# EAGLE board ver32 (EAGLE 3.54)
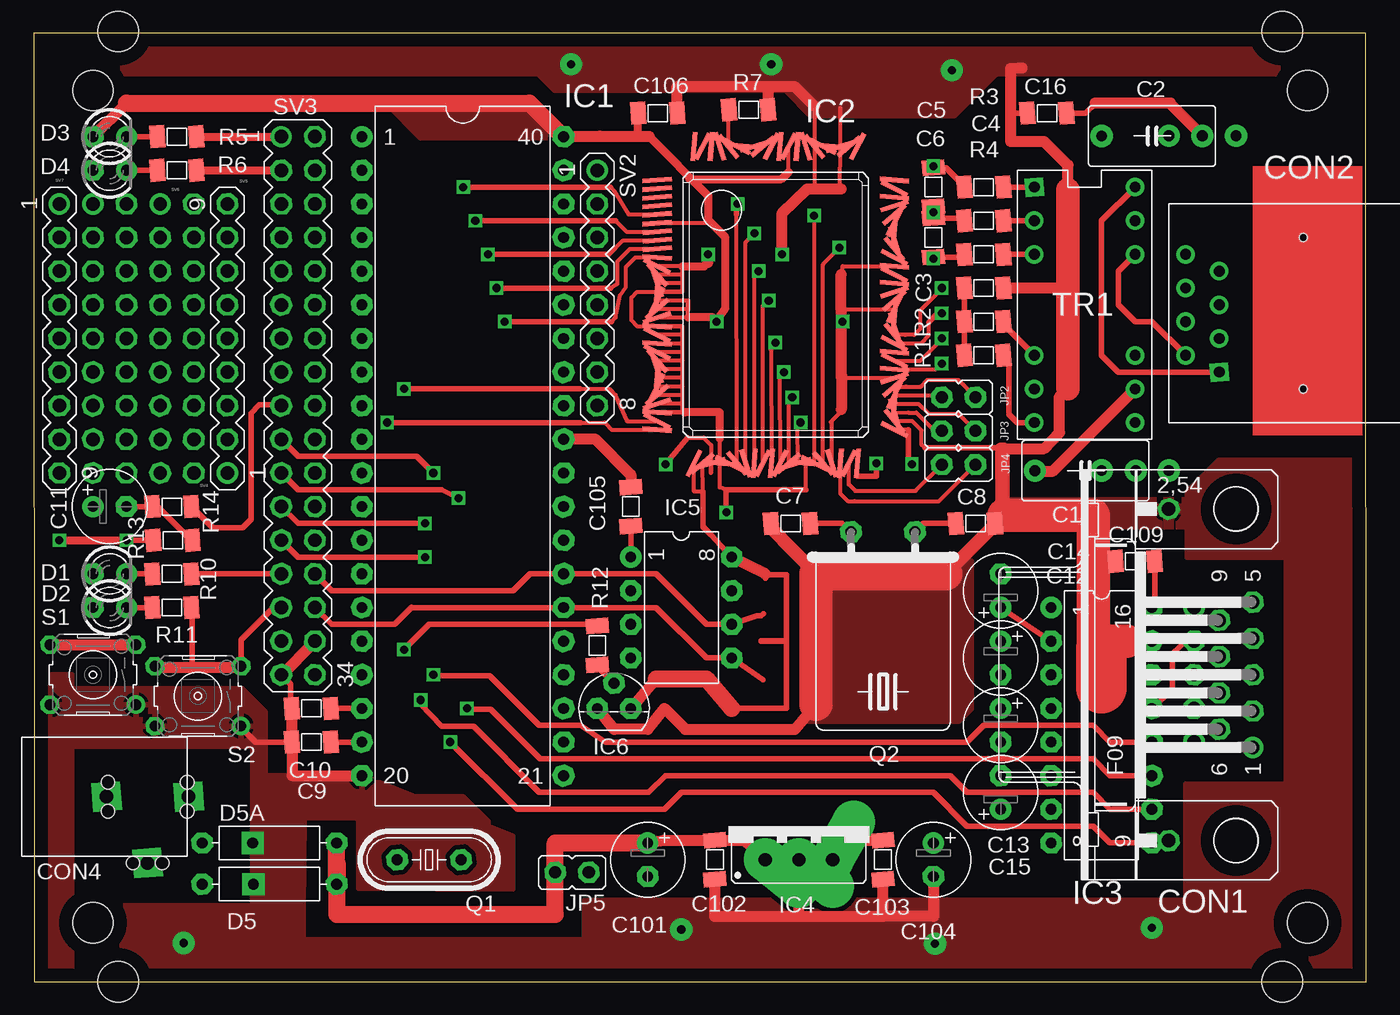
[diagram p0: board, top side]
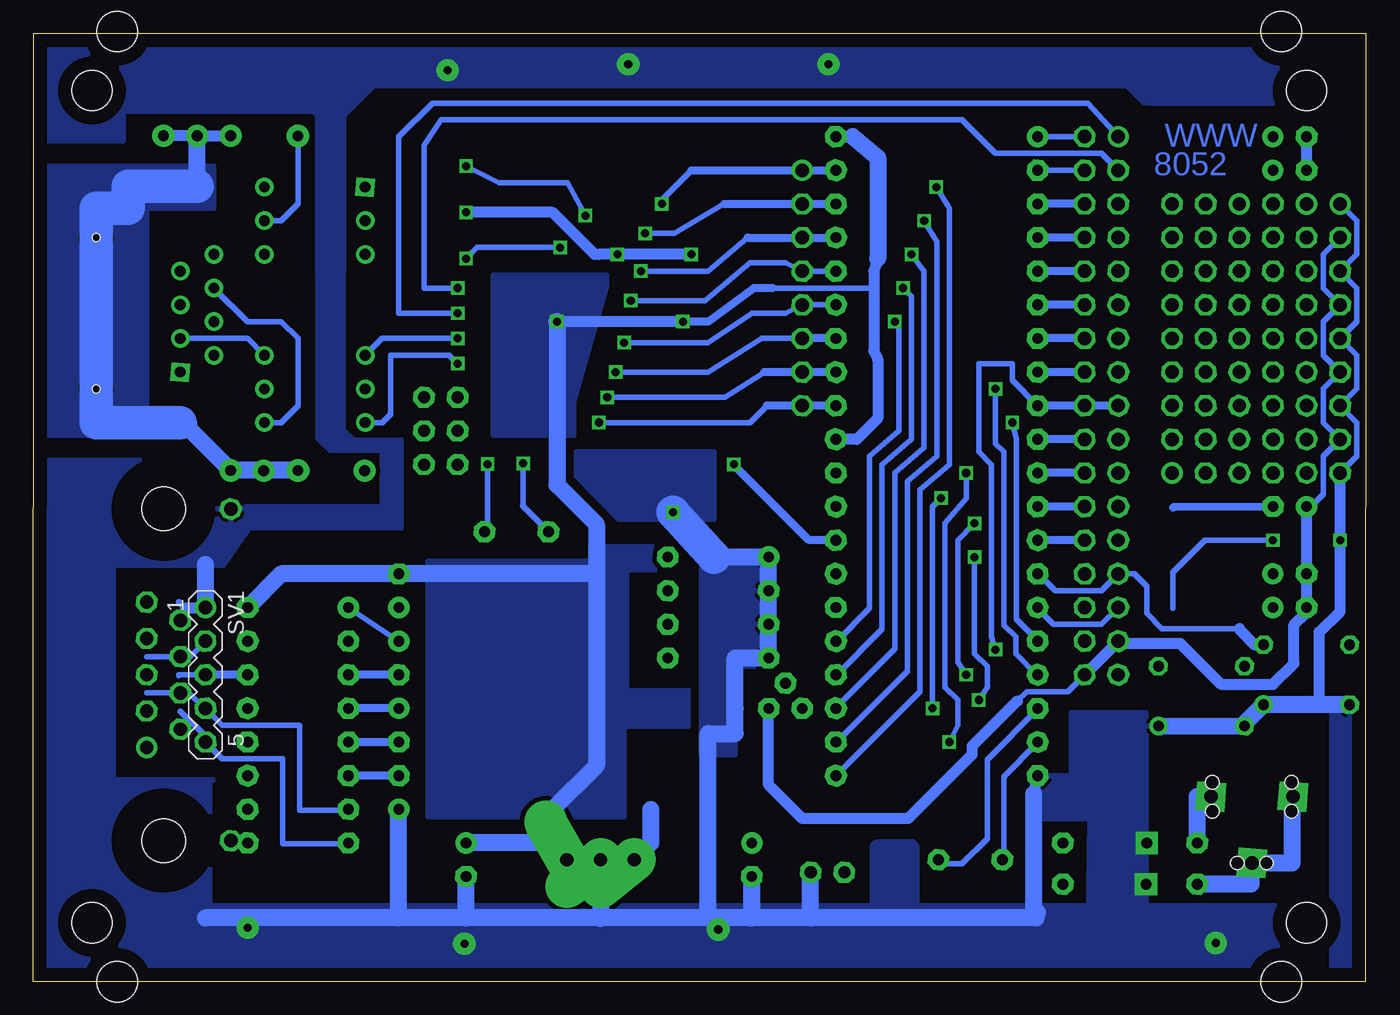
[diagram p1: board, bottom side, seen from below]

Size 100.68 x 71.65 mm. Coordinates in mm from the lower left corner, seen from the top.
Outline: 0.02,0.01 100.68,0 100.65,71.65 0,71.65 0.02,0.01
Copper layers used: Top, Bottom
Holes 3.05 mm at 4.47,67.32 4.47,4.45 96.23,4.45 96.23,67.32 6.38,0.01 6.38,71.76 94.32,71.76 94.32,0.01

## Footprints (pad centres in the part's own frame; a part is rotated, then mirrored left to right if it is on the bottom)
P75 = drill 0.813 pad 1.676 round:  -3.81,0;  3.81,0
06 = smd 1.143 x 1.702 rotated 4.4:  1.473,0 | smd 1.143 x 1.702 rotated 4.3:  -1.473,0
,5-6 = drill 0.813 pad 1.6 octagon:  1.27,0 | drill 0.813 pad 1.6 round:  -1.27,0
9H = drill 1.016 pad 1.6 round:  -5.486,-1.27 | drill 1.016 pad 1.6 octagon:  -2.743,-1.27;  0,-1.27;  2.743,-1.27;  5.486,-1.27;  -4.115,1.27;  -1.372,1.27;  1.372,1.27;  4.115,1.27;  -12.522,5.08;  12.522,5.08 | hole 3.302: -12.522,0; 12.522,0
45A = drill 0.813 pad 1.397 square:  5.08,1.27 | drill 0.813 pad 1.397 round:  2.54,1.27;  0,1.27;  -2.54,1.27;  3.81,-1.27;  1.27,-1.27;  -1.27,-1.27;  -3.81,-1.27 | hole 0.61: -5.08,7.62; 6.35,7.62
SOC = drill 1.016 pad 2.184 square:  0,5;  3.1,0;  -3.1,0 | hole 1.016: -3,1.1; -3,-1.1; 3,1.1; 3,-1.1; 1.1,5; -1.1,5
D3 = drill 0.813 pad 1.6 octagon:  -1.27,0 | drill 0.813 pad 1.6 round:  1.27,0
10 = drill 0.813 pad 1.6 octagon:  -5.08,0;  5.08,0
L40 = drill 0.813 pad 1.6 round:  -24.13,-7.62 | drill 0.813 pad 1.6 octagon:  -21.59,-7.62;  -19.05,-7.62;  -16.51,-7.62;  -13.97,-7.62;  -11.43,-7.62;  -8.89,-7.62;  -6.35,-7.62;  -3.81,-7.62;  -1.27,-7.62;  1.27,-7.62;  3.81,-7.62;  6.35,-7.62;  8.89,-7.62;  11.43,-7.62;  13.97,-7.62;  16.51,-7.62;  19.05,-7.62;  21.59,-7.62;  24.13,-7.62;  24.13,7.62;  21.59,7.62;  19.05,7.62;  16.51,7.62;  13.97,7.62;  11.43,7.62;  8.89,7.62;  6.35,7.62;  3.81,7.62;  1.27,7.62;  -1.27,7.62;  -3.81,7.62;  -6.35,7.62;  -8.89,7.62;  -11.43,7.62;  -13.97,7.62;  -16.51,7.62;  -19.05,7.62;  -21.59,7.62;  -24.13,7.62
P100 = smd 0.35 x 2.2 rotated 4.3:  -9.425,-8.965;  -3.575,-8.965 | smd 0.35 x 2.2 rotated 4.4:  -8.775,-8.965;  2.925,-8.965 | smd 0.35 x 2.2 rotated 4.5:  -8.125,-8.965;  9.425,-8.965 | smd 0.35 x 2.2 rotated 4.6:  -7.475,-8.965 | smd 0.35 x 2.2 rotated 4.7:  -6.825,-8.965;  -6.175,-8.965;  3.575,8.965 | smd 0.35 x 2.2 rotated 4.8:  -5.525,-8.965;  -2.925,8.965 | smd 0.35 x 2.2 rotated 4.9:  -4.875,-8.965;  -9.425,8.965 | smd 0.35 x 2.2 rotated 5:  -4.225,-8.965 | smd 0.35 x 2.2 rotated 26.8:  -2.925,-8.965 | smd 0.35 x 2.2 rotated 49.3:  -2.275,-8.965 | smd 0.35 x 2.2 rotated 71.8:  -1.625,-8.965 | smd 0.35 x 2.2 rotated 94.3:  -0.975,-8.965 | smd 0.35 x 2.2 rotated 116.8:  -0.325,-8.965 | smd 0.35 x 2.2 rotated 139.3:  0.325,-8.965 | smd 0.35 x 2.2 rotated 161.8:  0.975,-8.965 | smd 0.35 x 2.2 rotated 184.3:  1.625,-8.965 | smd 0.35 x 2.2 rotated 206.8:  2.275,-8.965 | smd 0.35 x 2.2 rotated 26.9:  3.575,-8.965 | smd 0.35 x 2.2 rotated 49.4:  4.225,-8.965 | smd 0.35 x 2.2 rotated 71.9:  4.875,-8.965 | smd 0.35 x 2.2 rotated 94.4:  5.525,-8.965 | smd 0.35 x 2.2 rotated 116.9:  6.175,-8.965 | smd 0.35 x 2.2 rotated 139.4:  6.825,-8.965 | smd 0.35 x 2.2 rotated 161.9:  7.475,-8.965 | smd 0.35 x 2.2 rotated 184.4:  8.125,-8.965 | smd 0.35 x 2.2 rotated 206.9:  8.775,-8.965 | smd 0.35 x 2.2 rotated 27.2:  9.425,8.965;  2.925,8.965 | smd 0.35 x 2.2 rotated 49.7:  8.775,8.965;  2.275,8.965 | smd 0.35 x 2.2 rotated 72.2:  8.125,8.965;  1.625,8.965 | smd 0.35 x 2.2 rotated 94.7:  7.475,8.965;  0.975,8.965 | smd 0.35 x 2.2 rotated 117.2:  6.825,8.965;  0.325,8.965 | smd 0.35 x 2.2 rotated 162.2:  5.525,8.965;  -0.975,8.965 | smd 0.35 x 2.2 rotated 139.7:  6.175,8.965;  -0.325,8.965 | smd 0.35 x 2.2 rotated 184.7:  4.875,8.965;  -1.625,8.965 | smd 0.35 x 2.2 rotated 207.2:  4.225,8.965;  -2.275,8.965 | smd 0.35 x 2.2 rotated 27.3:  -3.575,8.965 | smd 0.35 x 2.2 rotated 49.8:  -4.225,8.965 | smd 0.35 x 2.2 rotated 72.3:  -4.875,8.965 | smd 0.35 x 2.2 rotated 94.8:  -5.525,8.965 | smd 0.35 x 2.2 rotated 117.3:  -6.175,8.965 | smd 0.35 x 2.2 rotated 139.8:  -6.825,8.965 | smd 0.35 x 2.2 rotated 162.3:  -7.475,8.965 | smd 0.35 x 2.2 rotated 184.8:  -8.125,8.965 | smd 0.35 x 2.2 rotated 207.3:  -8.775,8.965 | smd 2.2 x 0.35 rotated 27.4:  -11.965,6.175 | smd 2.2 x 0.35 rotated 49.9:  -11.965,5.525 | smd 2.2 x 0.35 rotated 72.4:  -11.965,4.875 | smd 2.2 x 0.35 rotated 94.9:  -11.965,4.225 | smd 2.2 x 0.35 rotated 117.4:  -11.965,3.575 | smd 2.2 x 0.35 rotated 162.4:  -11.965,2.275 | smd 2.2 x 0.35 rotated 139.9:  -11.965,2.925 | smd 2.2 x 0.35 rotated 184.9:  -11.965,1.625 | smd 2.2 x 0.35 rotated 207.4:  -11.965,0.975 | smd 2.2 x 0.35 rotated 5:  -11.965,0.325 | smd 2.2 x 0.35 rotated 27.5:  -11.965,-0.325 | smd 2.2 x 0.35 rotated 50:  -11.965,-0.975 | smd 2.2 x 0.35 rotated 72.5:  -11.965,-1.625 | smd 2.2 x 0.35 rotated 95:  -11.965,-2.275 | smd 2.2 x 0.35 rotated 117.5:  -11.965,-2.925 | smd 2.2 x 0.35 rotated 140:  -11.965,-3.575 | smd 2.2 x 0.35 rotated 162.5:  -11.965,-4.225 | smd 2.2 x 0.35 rotated 185:  -11.965,-4.875 | smd 2.2 x 0.35 rotated 207.5:  -11.965,-5.525 | smd 2.2 x 0.35 rotated 4.3:  -11.965,-6.175 | smd 2.2 x 0.35 rotated 27:  11.965,-6.175 | smd 2.2 x 0.35 rotated 49.5:  11.965,-5.525 | smd 2.2 x 0.35 rotated 72:  11.965,-4.875 | smd 2.2 x 0.35 rotated 94.5:  11.965,-4.225 | smd 2.2 x 0.35 rotated 117:  11.965,-3.575 | smd 2.2 x 0.35 rotated 162:  11.965,-2.275 | smd 2.2 x 0.35 rotated 139.5:  11.965,-2.925 | smd 2.2 x 0.35 rotated 184.5:  11.965,-1.625 | smd 2.2 x 0.35 rotated 207:  11.965,-0.975 | smd 2.2 x 0.35 rotated 4.6:  11.965,-0.325 | smd 2.2 x 0.35 rotated 27.1:  11.965,0.325 | smd 2.2 x 0.35 rotated 49.6:  11.965,0.975 | smd 2.2 x 0.35 rotated 72.1:  11.965,1.625 | smd 2.2 x 0.35 rotated 94.6:  11.965,2.275 | smd 2.2 x 0.35 rotated 117.1:  11.965,2.925 | smd 2.2 x 0.35 rotated 139.6:  11.965,3.575 | smd 2.2 x 0.35 rotated 162.1:  11.965,4.225 | smd 2.2 x 0.35 rotated 184.6:  11.965,4.875 | smd 2.2 x 0.35 rotated 207.1:  11.965,5.525 | smd 2.2 x 0.35 rotated 4.7:  11.965,6.175
L16 = drill 0.813 pad 1.6 round:  -8.89,-3.81 | drill 0.813 pad 1.6 octagon:  -6.35,-3.81;  -3.81,-3.81;  -1.27,-3.81;  1.27,-3.81;  3.81,-3.81;  6.35,-3.81;  8.89,-3.81;  8.89,3.81;  6.35,3.81;  3.81,3.81;  1.27,3.81;  -1.27,3.81;  -3.81,3.81;  -6.35,3.81;  -8.89,3.81
XXS = drill 1.016 pad 3.251 offset:  -2.54,-2.54;  0,-2.54;  2.54,-2.54
L8 = drill 0.813 pad 1.6 round:  -3.81,-3.81 | drill 0.813 pad 1.6 octagon:  -1.27,-3.81;  1.27,-3.81;  3.81,-3.81;  3.81,3.81;  1.27,3.81;  -1.27,3.81;  -3.81,3.81
92 = drill 0.813 pad 1.6 octagon:  1.27,-0.635;  0,1.27;  -1.27,-0.635
1 = drill 0.914 pad 1.6 octagon:  0,-1.27;  0,1.27
49/S = drill 0.813 pad 1.6 octagon:  -2.413,0;  2.413,0
49U-H = drill 0.813 pad 1.6 octagon:  -2.413,-5.08;  2.413,-5.08
F-10XX = drill 0.813 pad 1.397 round:  -3.251,2.261 | drill 0.813 pad 1.397 octagon:  -3.251,-2.261;  3.251,2.261;  3.251,-2.261
05-1 = drill 1.016 pad 1.6 round:  -5.08,0 | drill 1.016 pad 1.6 octagon:  -2.54,0;  0,0;  2.54,0;  5.08,0
08-1 = drill 1.016 pad 1.6 round:  -8.89,0 | drill 1.016 pad 1.6 octagon:  -6.35,0;  -3.81,0;  -1.27,0;  1.27,0;  3.81,0;  6.35,0;  8.89,0
17-2 = drill 1.016 pad 1.6 round:  -20.32,-1.27 | drill 1.016 pad 1.6 octagon:  -17.78,-1.27;  -15.24,-1.27;  -12.7,-1.27;  -10.16,-1.27;  -7.62,-1.27;  -20.32,1.27;  -17.78,1.27;  -15.24,1.27;  -12.7,1.27;  -10.16,1.27;  -7.62,1.27;  -5.08,-1.27;  -5.08,1.27;  -2.54,-1.27;  0,-1.27;  2.54,-1.27;  5.08,-1.27;  7.62,-1.27;  10.16,-1.27;  -2.54,1.27;  0,1.27;  2.54,1.27;  5.08,1.27;  7.62,1.27;  10.16,1.27;  12.7,-1.27;  12.7,1.27;  15.24,-1.27;  17.78,-1.27;  20.32,-1.27;  15.24,1.27;  17.78,1.27;  20.32,1.27
09-1 = drill 1.016 pad 1.6 round:  -10.16,0 | drill 1.016 pad 1.6 octagon:  -7.62,0;  -5.08,0;  -2.54,0;  0,0;  2.54,0;  5.08,0;  7.62,0;  10.16,0
LE = drill 1.016 pad 1.6 round:  -10.16,-1.27 | drill 1.016 pad 1.6 octagon:  -7.62,-1.27;  -5.08,-1.27;  -2.54,-1.27;  0,-1.27;  2.54,-1.27;  -10.16,1.27;  -7.62,1.27;  -5.08,1.27;  -2.54,1.27;  0,1.27;  2.54,1.27;  5.08,-1.27;  7.62,-1.27;  5.08,1.27;  7.62,1.27;  10.16,-1.27;  10.16,1.27
IL16 = drill 0.813 pad 1.397 square:  -5.08,7.62 | drill 0.813 pad 1.397 round:  -5.08,5.08;  -5.08,2.54;  -5.08,-5.08;  -5.08,-7.62;  -5.08,-10.16;  2.54,7.62;  2.54,5.08;  2.54,2.54;  2.54,-5.08;  2.54,-7.62;  2.54,-10.16

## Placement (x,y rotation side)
C1  1nF/2kV  [P75]  79.45,38.6 180 top
C2  1nF/2kV  [P75]  84.48,63.88 180 top
C3  10nF  [06]  71.78,52.4 0 top
C4  10nF  [06]  71.78,57.48 0 top
C5  180  [06]  67.97,60.02 90 top
C6  180  [06]  67.97,56.2 270 top
C7  33  [06]  57.18,34.62 180 top
C8  33  [06]  71.15,34.62 0 top
C9  33  [06]  20.98,18.11 0 top
C10  33  [06]  20.98,20.64 0 top
C11  22M/16VT  [,5-6]  5.74,35.88 0 top
C12  22M/16VT  [,5-6]  73.05,24.46 270 top
C13  22M/16VT  [,5-6]  73.05,19.38 270 top
C14  22M/16VT  [,5-6]  73.05,29.54 90 top
C15  22M/16VT  [,5-6]  73.05,14.29 90 top
C16  10nF  [06]  76.54,65.6 0 top
C101  47M/25VT  [,5-6]  46.38,9.21 270 top
C102  100nF  [06]  51.46,9.21 90 top
C103  100nF  [06]  64.16,9.21 90 top
C104  100M/6.3VT  [,5-6]  67.97,9.21 270 top
C105  100nF  [06]  45.11,35.88 90 top
C106  100nF  [06]  47.14,65.6 180 top
C108  100nF  [B2,5]  50.19,20.64 0 top
C109  100nF  [06]  83.21,31.76 0 top
CON1  DB9  [9H]  90.83,23.18 90 top
CON2  RJ-45  [45A]  88.29,51.12 270 top
CON4  PWCON  [SOC]  8.6,13.98 180 top
D1  [D3]  5.74,30.8 0 top
D2  [D3]  5.74,28.27 0 top
D3  [D3]  5.74,63.83 0 top
D4  [D3]  5.74,61.29 0 top
D5  DIODE-10  [10]  17.81,7.37 0 top
D5A  DIODE-10  [10]  17.81,10.48 0 top
D6  1N4101  [7,5]  14.57,32.01 90 top
D7  1N4001  [7,5]  57.81,13.03 180 top
IC1  8052  [L40]  32.41,39.7 270 top
IC2  RTL8019AS  [P100]  56.06,51.12 270 top
IC3  MAX232  [L16]  80.67,19.38 270 top
IC4  7805  [XXS]  57.81,11.76 0 top
IC5  AT24C512  [L8]  48.92,28.27 270 top
IC6  DS1833  [92]  43.84,21.28 0 top
JP2  [1]  69.88,44.14 90 top
JP3  [1]  69.88,41.6 90 top
JP4  [1]  69.88,39.06 270 top
JP5  [1]  40.67,8.26 90 top
Q1  14.74 MHz  [49/S]  29.87,9.21 180 top
Q2  20MHz  [49U-H]  64.16,28.9 180 top
R1  49R9  [06]  71.78,47.31 180 top
R2  49R9  [06]  71.78,49.85 180 top
R3  10R  [06]  71.78,60.02 0 top
R4  10R  [06]  71.78,54.94 0 top
R5  1K0  [06]  10.82,63.83 0 top
R6  1K0  [06]  10.82,61.29 0 top
R7  27K  [06]  54,65.86 180 top
R8  10K  [06']  55.14,29.28 90 top
R9  10K  [06']  55.08,24.26 90 top
R10  1K0  [06]  10.44,30.8 0 top
R11  1K0  [06]  10.44,28.27 0 top
R12  1K0  [06]  42.57,25.41 90 top
R13  10K  [06]  10.5,33.34 0 top
R14  1K0  [06]  10.44,35.88 0 top
S1  [F-10XX]  4.47,23.18 180 top
S2  [F-10XX]  12.41,21.57 180 top
SV1  MA05-1  [05-1]  87.66,23.18 270 bottom
SV2  MA08-1  [08-1]  42.57,52.4 270 top
SV3  MA17-2  [17-2]  19.96,43.51 270 top
SV4  MA09-1  [09-1]  14.63,48.59 90 top
SV5  MA09-2  [LE]  10.82,48.59 270 top
SV6  MA09-2  [LE]  5.74,48.59 270 top
SV7  MA09-1  [09-1]  1.93,48.59 270 top
TR1  FC-22  [IL16]  80.67,52.4 0 top

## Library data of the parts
C1 C2 CON2 CON4 IC2 IC5 IC6 TR1 = network
C3-C6 C106 C109 R1-R7 R10-R14 = SMD
C7-C10 C16 C102 C103 C105 C108 = CAP
C11-C15 C101 C104 = POLCAP
CON1 = SUBD-A
D1-D4 = LED
D5 D5A D6 D7 R8 R9 = DISCRETE
IC1 = INTEL
IC3 = MAXIM
IC4 = V-REG
JP2-JP5 = JUMPS
Q1 Q2 = QUARTZ
S1 S2 = Key_omro
SV1-SV7 = CON-LSTB

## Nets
+5V: C11. C14. C103. C104. C105. C106. C108. C109. D1. D2. D3. D4. D7. IC1. IC2. IC3. IC4. IC5. IC6. R8. R9. SV3. SV7.
C1: CON2. TR1.
CTS: IC3. SV3.
GND: C3. C4. C5. C6. C7. C8. C9. C10. C15. C16. C101. C102. C103. C104. C105. C106. C108. C109. CON1. D6. IC1. IC2. IC3. IC4. IC5. IC6. JP5. R7. R13. S1. S2. SV1. SV3. SV7.
GNDA: C1. C2. C16.
LED0: IC2. R5. SV3.
LED1: IC2. R6. SV3.
N$1: CON2. TR1.
N$2: CON2. TR1.
N$3: CON2. TR1.
N$4: C1. TR1.
N$5: C3. R1. R2.
N$6: C2. TR1.
N$7: C6. IC2. R4.
N$8: IC2. R7.
N$9: C5. IC2. R3.
N$10: R3. TR1.
N$11: IC2. R1. TR1.
N$12: IC2. R2. TR1.
N$13: D4. R6.
N$14: D3. R5.
N$15: C7. IC2. Q2.
N$16: C10. IC1. Q1.
N$17: C9. IC1. Q1.
N$18: D1. R10.
N$19: IC6. R12.
N$20: D2. R11.
N$21: C11. D6. R13. R14.
N$22: C8. IC2. Q2.
N$23: CON4. D5.
N$24: CON4. D5A.
N$25: C101. C102. D5. D5A. D7. IC4. JP5.
N$29: C12. IC3.
N$30: C13. IC3.
N$31: C14. IC3.
N$32: C15. IC3.
N$33: C13. IC3.
N$34: C12. IC3.
N$37_IN: CON1. IC3. SV1.
N$39_IN: CON1. IC3. SV1.
N$40: R4. TR1.
N$41: C4. TR1.
N$42: IC2. JP4.
N$43: IC2. JP4.
N$44: IC2. JP2.
N$45: IC2. JP2.
N$46: IC2. JP3.
N$47: IC2. JP3.
N$51_OUT: CON1. IC3. SV1.
NS$40_OU: CON1. IC3. SV1.
P00: IC1. IC2. SV2.
P01: IC1. IC2. SV2.
P02: IC1. IC2. SV2.
P03: IC1. IC2. SV2.
P04: IC1. IC2. SV2.
P05: IC1. IC2. SV2.
P06: IC1. IC2. SV2.
P07: IC1. IC2. SV2.
P10: IC1. SV3.
P11: IC1. SV3.
P12: IC1. SV3.
P13: IC1. SV3.
P14: IC1. SV3.
P15: IC1. SV3.
P16: IC1. SV3.
P17: IC1. SV3.
P20: IC1. IC2.
P21: IC1. IC2.
P22: IC1. IC2.
P23: IC1. IC2.
P24: IC1. IC2.
P25: IC1. IC5. R9. SV3.
P26: IC1. IC5. R8. SV3.
P27: IC1. IC2.
P30: IC1. SV3.
P31: IC1. SV3.
P32: IC1. SV3.
P33: IC1. SV3.
P34: IC1. R10. S1. SV3.
P35: IC1. R11. S2. SV3.
RD\: IC1. IC2.
RST: IC1. R12. R14. SV3.
RTS: IC3. SV3.
RXD: IC3. SV3.
TXD: IC3. SV3.
WR\: IC1. IC2.

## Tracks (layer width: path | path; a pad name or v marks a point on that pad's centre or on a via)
+5V  (via drill 0.61 pad 1.02)
  Top 0.305: 60.28,39.16 60.25,42.29 60.22,42.29 61.1,43.16 | 65.02,54.05 61.11,54.05 61.03,50.82 60.97,50.78 | 47.09,57.3 50.94,57.3 50.95,57.48 | 61.11,45.6 65.02,45.6 | 60.97,50.78 65.02,50.8 | 60.97,50.78 60.99,50.8 | 49.44,50.74 49.44,51.45 | 49.44,50.8 47.09,50.8 | 47.09,50.15 49,50.15 49.44,50.17 49.44,50.74 | 49.44,51.45 47.09,51.45 | 49.44,50.74 49.44,50.8 | 49.44,51.45 49.44,50.8 | 51.59,49.92 51.33,50.17 | 50.55,37.02 50.53,39.16 | 49.88,39.16 49.88,37.02 50.55,37.02 | 50.57,36.99 50.55,37.02 | 57.03,63.09 57.03,61.17 57.05,61.17 | 50.95,59.38 50.74,59.38 50.95,59.44 49.5,60.61
  Top 0.406: 61.1,43.16 61.04,43.22 61.02,43.22 | 45.67,65.6 45.87,65.6 | 50.83,57.35 50.95,57.48 50.95,57.35 | 61,45.87 61.03,45.87 60.99,45.66 61.11,45.66 | 61.11,45.66 61.11,45.73 | 61.11,45.66 61.11,45.6 | 84.68,31.76 84.68,28.27 IC3. | 60.99,50.87 60.99,50.8 60.99,49.85 v61.11,49.85 | 55.27,30.75 55.27,30.49 | 55.27,30.75 55.27,30.8 | 55.27,30.75 55.14,30.75 56.86,30.75 56.86,25.73 | 56.86,25.73 54.95,25.73 54.95,25.74 55.08,25.74 56.86,25.74 56.86,25.73 | 56.86,25.73 56.86,20.64 52.73,20.64 | IC5. 51.16,33.78 50.57,34.36 50.57,36.99
  Top 0.61: 50.95,59.38 50.95,59.37 | 46.49,63.84 50.95,59.38 | 50.95,59.38 50.95,57.48 50.95,57.54 52.22,56.27 52.22,50.81 51.59,49.92 v51.59,49.85 | 51.33,50.17 49.44,50.17 | 57.05,61.17 56.49,60.61 49.5,60.61 | IC1. 40.07,63.86 | 45.67,65.6 45.64,65.6 45.64,63.86 42.77,63.86
  Top 0.813: 45.11,37.36 45.11,38.3 45.1,38.3 42.39,41 40.03,41 40.03,40.97 | 46.49,63.84 42.77,63.86 40.07,63.86 | 61,45.87 61.02,43.22 | 60.99,45.66 60.99,50.8 60.99,53.41 | 4.47,63.83 7.01,66.37 | 64.16,10.69 61.94,10.69 IC4. | 55.27,30.8 IC5. | 45.11,20.64 47.02,22.87
  Top 1.27: 52.73,20.64 50.83,22.87 47.02,22.87 | IC1. 40.01,63.81 37.45,66.37 7.01,66.37
  Bottom 0.406: 1.93,56.2 3.2,54.94 3.2,52.4 1.93,51.12 3.2,49.85 3.2,47.31 1.93,46.05 3.2,44.77 3.2,42.23 1.93,40.97 3.2,39.7 3.2,36.84 4.15,35.88 C11. | SV3. 22.5,21.91 25.62,21.91 26.31,21.22 26.25,21.28 | 37.17,52.4 44.79,52.4
  Bottom 0.61: v51.59,49.85 49.68,49.85 46.25,52.4 44.79,52.4
  Bottom 0.813: 40.03,40.97 38.44,40.97 36.86,42.55 36.86,47 37.17,47.63 37.17,52.4 37.17,53.66 36.86,54.62 | IC1. 38.76,63.83 | v51.59,49.85 v61.11,49.85 | 4.47,61.29 4.47,63.83 | IC4. 61.62,10.48 | SV3. 18.69,25.73 18.63,25.73 18.44,25.53 14,25.53 10.91,22.45 7.01,22.45 7.01,22.46 5.44,24.04 5.44,26.96 4.47,27.92 4.47,28.27 4.47,30.8 C11. | 45.11,20.64 45.11,14.87 42.57,12.33 34.57,12.33 29.74,17.15 29.74,17.79 26.31,21.22
  Bottom 1.27: 36.86,54.62 36.86,62.24 38.76,63.83 | v61.11,49.85 61.11,37.52 58.13,34.54 58.13,16.33 61.49,12.96 | 61.62,10.48 C104. | 61.62,10.48 61.62,10.42 | 61.62,10.48 61.62,13.03 | 58.12,30.79 58.12,30.8 73.05,30.8 81.93,30.8 84.48,28.25 IC3.
  pour Bottom (isolate 0.356): 70.83,12.45 70.83,31.76 56.03,31.76 56.03,12.45
  pour Bottom (isolate 0.356, no thermals): 51.27,19.31 58.57,19.31 58.57,19.63 58.57,32.84 52.1,32.84 52.1,31.12 55.84,31.12 55.84,31.19 55.84,21.98 51.14,21.98 51.21,21.98 51.21,19.31
  pour Bottom (isolate 0.356): 57.37,53.35 65.87,53.35 65.87,41.28 59.84,41.28 59.84,43.76 57.37,52.52
  pour Top (isolate 0.356): 40.03,63.76 29.24,63.76 26.7,66.3 37.49,66.3
C1
  Bottom 0.406: TR1. 81.94,42.23 80.67,43.51 80.67,48.59 81.94,49.85 84.48,49.85 87.02,52.4
CTS  (via drill 0.61 pad 1.02)
  Top 0.406: 84.48,18.11 81.31,18.11 80.04,19.37 71.78,19.37 70.51,18.11 43.21,18.11 41.3,19.37 38.19,19.37 34.44,23.12 30.25,23.12 30.23,23.15 30.18,23.15 v30.19,23.18 | 18.69,35.88 19.96,34.62 v29.55,34.62
  Bottom 0.406: v30.19,23.18 30.82,24.14 30.82,33.34 v29.55,34.62
GND  (via drill 0.61 pad 1.02, 0.61 pad 1.68, 0.81 pad 1.68)
  Top 0.305: 60.93,65.97 60.93,63.09 60.91,59.97 | 47.09,54.05 49,54.05 49,54.03 49,53.4 | 47.09,53.4 49,53.4 | 47.09,52.75 49,52.75 49,52.76 | 49,52.76 49,53.4 | 47.09,52.1 49,52.1 | 49,52.1 49,52.76 | 49,52.1 45.59,52.1 45.16,51.67 45.16,49.97 45.62,49.49 49,49.49 | 47.09,49.5 49,49.5 49,49.49 | 47.09,48.85 49,48.85 | 47.09,48.2 47.1,48.19 49,48.19 | 49,48.85 49,49.49 | 47.09,47.55 49,47.55 49,47.56 | 49,48.19 49,48.85 | 47.09,46.9 49,46.9 49,46.92 | 49,47.56 49,48.19 | 47.09,46.25 49,46.25 49,46.26 | 49,46.92 49,47.56 | 49,45.6 47.09,45.6 | 49,46.26 49,46.92 | 47.09,44.95 49,44.95 49,44.97 | 49,45.6 49,46.26 | 49,45.6 | 47.09,44.3 49,44.3 49,44.31 | 49,44.97 49,45.6 | 47.09,43.65 49,43.65 49,43.64 | 49,44.31 49,44.97 | 49,43.64 49,44.31 | 49,43.64 49,43 47.09,43 49.17,43 | 65.02,42.35 65.56,42.35 66.37,42.35 67.08,41.64 67.08,40.57 67.34,40.32 67.34,40.33 | 51.84,39.16 51.84,39.12 | 51.84,39.16 51.84,41.03 | 51.84,39.16 51.83,39.16 51.83,37.35 52.29,37.16 | 58.34,39.15 58.33,39.16 58.33,37.16 | 58.98,59.93 58.98,63.09 58.98,66.15 59.08,66.25 | 55.4,67.62 55.47,67.62
  Top 0.406: 17.18,18.11 C9. | 17.18,18.11 17.17,18.09 | 17.18,18.11 16.78,18.11 15.65,19.24 15.66,19.31 | C4. 70.26,57.48 70.05,57.68 C6. | C6. 67.97,57.6 | 61,59.88 60.99,59.89 60.91,59.97 | v67.97,58.11 C5. v67.97,58.11 | v67.97,58.11 C6. | 73.81,68.98 74.38,69.22 | 73.81,65.6 C16. | C109. 80.35,31.76 80.04,31.44 | 73.05,40.33 67.34,40.33 | 72.62,34.62 72.73,34.62 73.05,34.93 | 45.11,32.08 C105. | 57.81,7.95 57.81,7.74 | 55.4,65.6 55.47,65.6 R7. | 18.69,23.18 19.39,22.49 19.39,20.64 | v7.01,33.34 R13. | 58.33,37.16 52.29,37.16 52.29,35.44
  Top 0.61: 50.93,54.31 50.65,54.03 49,54.03 | 49.17,43 51.84,43 51.84,41.03 | v1.93,33.34 v7.01,33.34
  Top 0.813: 24.79,15.56 19.51,15.56 C9. C10. 19.39,20.64 | 60.99,59.89 58.45,59.89 56.54,58.05 v56.54,54.94 | 50.93,54.31 v50.95,54.94 | 74.68,69.02 73.81,68.98 73.81,65.6 73.81,63.44 76.35,63.44 78.13,61.67 78.13,59.82 | 84.48,25.73 82.83,25.73 82.7,25.79 82.7,25.73 82.58,25.73 80.67,25.22 | 78.13,52.4 73.25,52.4 | 78.13,44.77 77.5,44.2 77.5,41.47 76.35,40.27 73.3,40.27 | 73.3,40.27 73.3,35.25 | 73.3,40.27 73.3,40.33 73.05,40.33 73.05,34.93 | 57.81,9.21 57.81,7.95 57.81,4.92 | C102. 51.46,4.92 57.81,4.92 | 59.08,20.96 57.49,19.06 49.24,19.06 47.65,20.64 46.38,19.06 43.84,19.06 IC6. | 57.81,4.92 64.16,4.92 64.16,4.94 | 64.16,4.94 C103. | 64.16,4.94 67.97,4.94 67.97,7.95 | 58.98,66.15 58.93,66.15 57.45,67.62 55.47,67.62 R7. | 55.4,67.62 48.62,67.62 C106. | 18.69,23.18 18.69,23.12 21.23,25.66 21.23,25.73
  Top 1.016: 68.92,30.8 72.73,34.62 | 55.7,34.62 55.7,34.3 59.08,30.8
  Top 1.778: 78.13,59.82 78.13,52.4 78.13,44.77
  Top 2.54: 82.58,25.73 80.04,25.73 80.04,31.44 80.04,35.25 73.3,35.25 73.37,35.25 | 68.92,30.8 59.08,30.8 59.08,20.96
  Top 3.81: 80.67,25.22 80.67,22.17
  Bottom 0.406: 1.93,58.74 0.66,57.48 0.66,54.94 1.93,53.66 0.66,52.4 0.66,49.85 1.93,48.59 0.66,47.31 0.66,44.77 1.93,43.51 0.66,42.23 0.66,39.7 SV7. | 14.57,28.2 14.57,30.93 12.15,33.34 v7.01,33.34 | 3.52,20.96 1.3,20.96 1.22,20.92 | 7.72,20.92 7.65,20.92 7.65,20.96 | v56.54,54.94 56.41,54.94 56.29,54.81 56.16,54.94 | 89.56,28.67 89.69,28.67 89.69,28.71 89.18,28.2 | 87.66,28.27 87.66,28.2
  Bottom 0.813: 24.79,15.56 25.11,14.17 | 1.93,27.97 1.96,27.97 1.93,27.95 | 3.52,20.96 3.52,26.41 1.93,27.95 | v67.97,58.11 61.43,58.11 58.24,54.92 57.94,54.94 56.41,54.94 56.35,54.94 | 56.35,54.94 56.16,54.94 | v50.95,54.94 56.35,54.94 | 87.66,28.2 89.18,28.2 | SV7. v1.93,33.34 1.93,27.97 | 1.93,27.95 1.93,27.97
  Bottom 1.27: 25.11,14.17 25.11,4.96 | 15.66,19.31 15.61,19.25 15.6,19.26 15.58,19.25 9.16,19.31 9.16,19.5 7.77,20.89 7.72,20.92 | 1.22,20.92 7.65,20.92 | 57.81,9.21 57.81,4.77 | 49.24,32.08 45.11,32.08 45.11,29.53 45.11,27 45.11,24.46 47.65,24.46 47.65,20.64 47.65,18.74 49.68,18.74 49.68,4.83 | 73.05,4.83 87.66,4.83 | 73.05,4.83 C15. | 67.97,4.83 73.05,4.83 | 67.97,4.83 67.97,7.95 | 46.38,7.95 46.38,4.83 46.51,4.83 | 49.68,4.83 67.97,4.83 | 46.51,4.83 49.68,4.83 | 24.79,5.21 24.92,5.21 24.92,4.83 41.94,4.83 | 41.94,4.83 46.51,4.83 | 41.94,4.83 41.94,8.26 | 87.66,28.27 87.66,31.5
  Bottom 2.54: 49.24,32.08 v52.32,35.45
  other vias: 84.48,4.07 48.92,3.94 11.33,2.93 68.1,2.86 40.6,69.29 55.71,69.29 69.37,68.84 16.54,10.48 16.6,7.37
  pour Top (isolate 0.356): 58.45,31.76 70.83,31.76 70.83,20.64 69.88,19.69 58.45,19.69
  pour Top (isolate 0.356): 0.28,71.13 100.36,71.13 100.36,63.51 93.94,63.51 93.94,68.59 72.69,68.59 69.52,65.41 58.72,65.41 56.82,67.32 39.4,67.32 38.13,68.59 0.28,68.59
  pour Bottom (isolate 0.356): 0.34,5.72 87.34,5.72 87.34,15.25 87.02,15.25 94.64,15.25 94.64,31.44 86.32,31.44 84.48,34.11 84.42,34.11 87.02,36.84 89.56,39.38 100.36,39.38 100.36,0.33 0.34,0.33
  pour Bottom (isolate 0.356): 0.34,0.33 0.34,20.33 2.57,20.33 2.57,0.33
  pour Bottom (isolate 0.356): 16.6,20.33 22.25,20.33 22.25,15.56 24.79,15.56 24.66,12.33 20.85,12.33 20.98,1.91 16.6,1.91
  pour Bottom (isolate 0.356): 49.24,40.01 59.63,40.01 59.63,38.17 56.45,34.93 49.23,34.93
  pour Bottom (isolate 0.356): 45.11,32.08 50.19,32.08 50.19,17.15 47.65,17.15 47.65,23.82 45.11,23.82
  pour Bottom (isolate 0.356): 52.1,21.6 56.03,21.6 56.03,31.76 70.76,31.76 70.76,15.25 52.1,15.25
  pour Top (isolate 0.356): 89.56,39.38 100.36,39.38 100.36,0.33 0.34,0.33 0.34,5.72 20.35,5.72 20.35,3.18 41.62,3.18 41.62,6.17 87.02,6.17 87.02,14.93 94.64,14.93 94.64,32.08 87.15,32.08 87.15,36.96
  pour Top (isolate 0.356): 0.34,22.14 15.67,22.16 17.49,20.34 17.49,15.56 24.79,15.56 36.16,10.99 36.16,6.99 24.54,7.06 24.54,12.39 20.41,12.39 20.35,5.41 16.54,5.41 16.54,17.79 0.34,17.79
  pour Top (isolate 0.356): 0.34,17.79 0.34,0.33 2.57,0.33 2.57,18.11 0.34,18.11 0.34,17.47
  pour Top (isolate 0.356): 0.34,17.79 2.88,17.79 2.88,5.41 0.34,5.41
  pour Top (isolate 0.356): 0.34,23.18 0.34,0.33 2.88,0.33 2.88,23.18
  pour Bottom (isolate 0.356): 0.03,66.36 16.26,66.36 16.74,66.38 18.02,67.66 75.02,67.63 77.24,65.41 77.23,65.41 77.24,41.66 76.48,40.9 72.86,40.9 72.86,34.3 87.97,34.3 87.97,35.88 74.26,35.88 74.26,40.14 78.26,40.14 79.15,41.03 79.18,65.43 79.5,65.74 93.88,65.73 93.88,63.51 100.36,63.51 100.36,71.13 0.03,71.13
  pour Top (isolate 0.356): 73.3,36.2 87.53,36.2 87.53,34.55 73.3,34.55
  pour Bottom (isolate 0.356): 34.38,10.17 34.38,10.1 36.86,10.1 36.86,3.75 36.86,3.82 34.38,3.82
  pour Top (isolate 0.254): 24.79,15.56 26.38,13.98 32.41,13.98 34.32,12.07 34.32,11.44 34.25,11.37 24.79,11.37
GNDA  (via drill 0.81 pad 1.68)
  Top 0.406: 78.02,65.6 79.46,65.6 80.23,66.37
  Top 0.813: 80.2,66.37 80.23,66.37 85.88,66.37 85.88,66.3 v88.29,63.89 88.29,63.88
  Bottom 0.813: v80.67,38.62 v85.75,38.62 | v85.75,63.89 v88.29,63.89 v90.83,63.89
  Bottom 1.27: 83.26,38.6 80.43,38.62 v80.67,38.62 v85.75,38.62 89.31,42.17 88.93,42.17 89.56,42.23 | 88.29,60.08 88.29,60.21 | 88.29,60.21 88.29,63.88 | 88.29,60.21 88.42,59.95
  Bottom 2.54: 89.56,42.23 95.91,42.23 95.91,58.43 93.5,58.43 93.5,60.08 88.29,60.08
  pour Bottom (isolate 0.356): 92.1,41.28 100.36,41.28 100.36,61.6 87.02,61.6 87.02,58.43 92.1,58.43
LED0  (via drill 0.61 pad 1.02)
  Top 0.305: 65.02,48.2 67.01,48.2 67.59,48.78 67.59,49.79 67.65,49.85
  Top 0.406: v68.61,50.49 68.29,50.49 67.65,49.85
  Top 0.61: 12.29,63.83 18.69,63.83
  Bottom 0.406: v68.61,50.49 73.05,50.49 73.05,63.83 70.51,66.37 20.98,66.37 18.69,63.83
LED1  (via drill 0.61 pad 1.02)
  Top 0.305: 65.02,48.85 65.88,48.85 65.86,48.85 65.84,48.85 66.52,48.85 66.95,49.28 66.95,50.68 68.61,52.33
  Top 0.406: v68.61,52.4 68.61,52.33
  Top 0.61: 12.29,61.29 18.69,61.29
  Bottom 0.406: v68.61,52.4 71.15,52.4 71.15,63.19 69.88,65.1 30.51,65.1 27.97,62.55 19.96,62.55 18.69,61.29
N$1
  Top 0.406: 87.02,47.31 84.48,49.85 83.21,49.85 81.94,51.12 81.94,53.66 83.21,54.94
N$2
  Top 0.406: 89.56,46.05 81.94,46.05 80.67,47.31 80.67,57.48 83.21,60.02
N$3
  Bottom 0.406: 89.56,48.59 84.48,48.59 83.21,47.31
N$4
  Top 0.813: C1. 75.41,38.62 75.41,38.56 77,38.56 83.21,44.77
N$5
  Top 0.406: 70.31,47.31 70.31,49.65 70.51,49.85 70.31,49.85 70.31,52.19 70.51,52.4 C3.
N$6
  Bottom 0.406: 83.21,57.48 81.94,57.48 80.67,58.74 C2.
N$7  (via drill 0.61 pad 1.02)
  Top 0.305: 60.88,55.43 | 60.88,55.43 | 59.63,39.16 59.63,54.18 60.88,55.43
  Top 0.406: R4. 70.26,54.94 70.05,54.73 67.97,54.73 67.65,54.94 v67.97,54.62 | v60.86,55.44 60.89,55.44 60.88,55.43
  Bottom 0.406: v60.86,55.44 60.88,55.46 67.15,55.46 v67.97,54.62
N$8
  Top 0.305: 52.46,65.84 52.45,65.84 | 52.46,65.84 | 52.48,63.09 52.48,65.81 52.46,65.84
  Top 0.406: 52.53,65.86 52.48,65.86 52.46,65.84
N$9  (via drill 0.61 pad 1.02)
  Top 0.305: 58.93,57.77 | 58.93,57.77 58.93,57.78 | 58.98,39.16 58.98,57.77 58.93,57.77
  Top 0.406: R3. 70.38,60.02 68.91,61.49 67.97,61.49 v67.97,61.6 | 58.93,57.78 v58.95,57.86
  Bottom 0.406: v58.95,57.86 58.95,57.84 60.3,60.33 65.49,60.33 v67.97,61.6
N$10
  Top 0.406: 75.72,60.02 75.59,60.02 73.25,60.02
N$11  (via drill 0.61 pad 1.02)
  Top 0.305: 68.55,46.6 68.54,46.62 68.48,46.62 68.11,46.25 65.02,46.25
  Top 0.406: 75.59,42.23 74.32,42.23 73.69,42.87 73.69,46.68 73.05,47.31 R1. | 68.54,46.62 v68.61,46.68
  Bottom 0.406: 75.59,42.23 74.32,42.23 73.69,42.87 73.69,47.31 69.24,47.31 v68.61,46.68
N$12  (via drill 0.61 pad 1.02)
  Top 0.305: v68.6,48.59 v68.61,48.59 | 68.57,48.55 68.58,48.55 68.61,48.52 66.98,46.9 65.02,46.9
  Top 0.406: R2. 73.05,49.85 75.59,47.31 | v68.61,48.59 68.64,48.62 | 68.57,48.55 v68.6,48.59
  Bottom 0.406: 75.59,47.31 74.32,48.59 v68.61,48.59
N$13
  Top 0.406: 6.69,61.29 D4. R6.
N$14
  Top 0.406: D3. R5.
N$15  (via drill 0.61 pad 1.02)
  Top 0.305: 62.23,38.18 IC2. | v63.66,39.15 63.63,39.15
  Top 0.406: Q2. 61.75,33.92 61.05,34.62 C7. | 63.63,39.15 v63.65,39.15 63.65,38.18 62.23,38.18
  Bottom 0.406: v63.66,39.15 63.68,39.17 63.68,36.01 63.72,35.95 Q2.
N$16
  Top 0.406: 24.79,20.64 22.45,20.64
  Bottom 0.406: 32.28,9.21 32.41,9.21 32.41,8.9 30.51,8.9 28.6,10.8 28.6,16.77 24.79,20.58 24.79,20.64
N$17
  Top 0.406: 24.79,18.11 22.45,18.11
  Bottom 0.406: Q1. 27.33,9.21 27.33,15.5 24.79,18.04 24.79,18.11
N$18
  Top 0.406: D1. R10.
N$19
  Top 0.406: R12. 42.57,23.82 43.84,22.55
N$20
  Top 0.406: D2. R11.
N$21
  Top 0.406: 12.03,33.34 11.98,33.34 11.9,33.34 9.36,35.88 R14. 8.97,35.87 8.92,35.82 8.85,35.88 7.01,35.88
  Bottom 0.61: 7.01,35.88 14.57,35.82
N$22  (via drill 0.61 pad 1.02)
  Top 0.305: 66.08,41.7 65.02,41.7
  Top 0.406: C8. 67.21,34.62 66.57,33.98 | 66.34,39.12 66.38,39.12 | v66.34,39.1 66.34,39.12 | 66.08,41.7 66.08,39.12 66.34,39.12
  Bottom 0.406: v66.34,39.1 66.34,34.23 66.57,33.98
N$23
  Bottom 1.27: 5.5,13.98 5.55,13.98 5.55,8.98 8.6,8.98 8.66,8.98 8.66,7.37 12.73,7.37
N$24
  Bottom 1.27: 12.73,10.48 12.73,13.98 CON4.
N$25
  Top 0.813: 55.27,9.21 53.68,10.69 51.46,10.69 47.65,10.69 C101.
  Top 1.27: D5. 22.89,5.09 39.4,5.09 JP5. 39.4,10.48 C101. | D5. 22.89,8.9 | 22.89,8.9 D5A. | 22.95,7.37 22.95,7.31 | D5. 22.95,7.37 | 22.89,8.9 22.95,8.9 22.95,7.37
  Bottom 1.27: 54,13.03 54,10.48 55.27,9.21
N$29
  Bottom 0.406: C12. 76.86,28.27
N$30
  Bottom 0.61: C13. 76.86,20.64
N$31
  Top 0.406: C14. 76.86,25.73
N$32
  Bottom 0.61: 73.05,15.56 76.86,15.56
N$33
  Bottom 0.61: 73.05,18.11 76.86,18.11
N$34
  Bottom 0.61: 73.05,23.18 76.86,23.18
N$37_IN
  Bottom 0.406: SV1. 87.66,18.04 | 89.56,20.44 87.66,18.55 SV1. | SV1. 86.39,16.84 81.81,16.84 81.81,10.42 76.73,10.42 76.73,10.48 76.86,10.48
N$39_IN
  Top 0.406: 87.66,25.73 87.02,25.73 86,24.77 86,22.11 84.48,20.58 84.48,20.64
  Bottom 0.406: 87.66,25.73 87.66,25.66 88.8,24.56 92.1,24.56
N$40
  Top 0.406: 75.72,54.94 75.59,54.94 73.25,54.94
N$41
  Top 0.406: 75.59,57.48 75.59,57.35 75.46,57.48 73.25,57.48
N$42
  Top 0.305: 60.93,39.16 60.93,36.86 61.51,36.29 62.03,36.29 62.03,36.3 68.39,36.3 JP4.
N$43
  Top 0.305: 61.58,39.16 61.58,37.56 62.08,37.07 66.61,37.07 68.61,39.06
N$44
  Top 0.305: 65.9,44.95 65.89,44.95 | 65.02,44.95 65.9,44.95 | 65.9,44.95 67.01,44.95 67.51,45.45 69.85,45.45 71.15,44.15 71.15,44.14
N$45
  Top 0.305: 68.61,44.12 68.61,44.11 | 68.61,44.12 JP2. | 68.61,44.12 68.42,44.3 68.4,44.3 68.38,44.28 68.36,44.3 65.02,44.3
N$46
  Top 0.305: 71.15,41.6 69.86,42.88 67.61,42.88 66.85,43.64 65.02,43.64 65.02,43.65
N$47
  Top 0.305: 66.07,42.98 66.08,42.98 | 65.02,43 66.07,42.98 | 67.97,41.6 67.97,41.69 66.68,42.98 66.07,42.98
  Top 0.406: 67.97,41.6 JP3.
N$51_OUT
  Bottom 0.406: 89.69,23.18 89.56,23.18 | 87.66,23.18 89.69,23.18 | 89.69,23.18 89.69,23.12 | 84.48,23.18 84.61,23.18 84.61,23.12
  Bottom 0.61: 84.61,23.18 87.66,23.18
NS$40_OU
  Bottom 0.406: 92.1,21.81 88.93,21.81 87.66,20.58 87.66,20.64 86.39,19.37 80.54,19.37 80.54,12.96 76.99,12.96 76.86,13.03
P00  (via drill 0.61 pad 1.02)
  Top 0.305: 53.13,39.16 53.11,57.98 53.1,57.97 53.1,57.95 | 53.1,58.67 v53.18,58.74
  Top 0.406: 53.1,57.97 53.1,58.67
  Bottom 0.305: v53.18,58.74 53.18,59.06
  Bottom 0.406: 53.18,59.06 50.95,61.29
  Bottom 0.61: 40.03,61.29 42.57,61.29 50.95,61.29
P01  (via drill 0.61 pad 1.02)
  Top 0.305: 54.43,56.51 54.43,56.5 53.78,55.85 53.78,39.16
  Top 0.406: 54.43,56.51 v54.44,56.52
  Bottom 0.406: 48.48,58.74 52.22,56.52 v54.44,56.52
  Bottom 0.61: 40.03,58.74 42.57,58.74 48.48,58.74
P02  (via drill 0.61 pad 1.02)
  Top 0.305: 54.43,39.16 | 54.79,53.67 54.43,53.31 54.43,39.16
  Top 0.406: 54.79,53.67 v54.76,53.66
  Bottom 0.406: 46.7,56.2 49.68,53.66 v54.76,53.66
  Bottom 0.61: 40.03,56.2 42.57,56.2 46.7,56.2
P03  (via drill 0.61 pad 1.02)
  Top 0.305: 55.09,39.15 | 55.08,39.16 55.09,39.15 | 55.51,51.45 55.09,51.02 55.09,39.15
  Top 0.406: 55.51,51.45 v55.52,51.44
  Bottom 0.406: 40.03,53.66 42.57,53.66 43.84,54.3 46.51,54.3 49.94,51.44 v55.52,51.44
P04  (via drill 0.61 pad 1.02)
  Top 0.305: 55.71,47.82 55.73,39.16
  Top 0.406: v56.03,48.27 55.71,47.82
  Bottom 0.406: 40.03,51.12 42.57,51.12 43.84,50.49 46.38,50.49 49.68,48.27 v56.03,48.27
P05  (via drill 0.61 pad 1.02)
  Top 0.305: v56.67,46.05 56.67,46.02 56.67,46.01 56.36,45.7 56.38,39.16
  Bottom 0.406: 42.57,48.59 45.62,48.59 49.68,46.05 v56.67,46.05
  Bottom 0.61: 40.03,48.59 42.57,48.59
P06  (via drill 0.61 pad 1.02)
  Top 0.305: v57.3,44.14 v57.3,44.13 57.31,44.12 57.01,43.81 57.03,39.16
  Bottom 0.406: 45.43,46.05 48.41,44.14 v57.3,44.14
  Bottom 0.61: 40.03,46.05 42.57,46.05 45.43,46.05
P07  (via drill 0.61 pad 1.02)
  Top 0.305: v57.94,42.23 57.94,42.23 57.94,42.22 57.66,41.94 57.68,39.16
  Bottom 0.406: 45.24,43.51 46.51,42.23 v57.94,42.23
  Bottom 0.61: 40.03,43.51 SV2. 45.24,43.51
P10
  Bottom 0.406: 25.11,63.83 24.79,63.83 21.23,63.83
P11
  Bottom 0.406: 21.23,61.29 24.79,61.29
P12
  Bottom 0.61: 21.23,58.74 24.79,58.74
P13
  Bottom 0.61: 21.23,56.2 24.79,56.2
P14
  Bottom 0.61: 21.23,53.66 24.79,53.66
P15
  Bottom 0.61: 21.23,51.12 24.79,51.12
P16
  Bottom 0.61: 21.23,48.59 24.79,48.59
P17
  Bottom 0.61: 21.23,46.05 24.79,46.05
P20  (via drill 0.61 pad 1.02)
  Top 0.305: 47.09,57.95 44.95,57.95 44.95,57.96 43.87,59.7 43.56,60
  Top 0.406: v32.45,60.02 43.38,60 43.56,60
  Bottom 0.406: 33.68,29.09 33.68,37.16 31.46,39.06 31.46,58.43 v32.45,60.02 | 33.68,29.09 33.68,29.03 | 40.03,15.56 33.68,21.91 33.68,29.09
P21  (via drill 0.61 pad 1.02)
  Top 0.305: 43.97,57.48 43.97,57.46 44.78,56.65 47.09,56.65
  Top 0.406: v33.36,57.48 43.97,57.48
  Bottom 0.406: v33.36,57.48 32.41,55.89 32.41,39.7 34.63,37.79 34.63,23.44 40.03,18.04 40.03,18.11
P22  (via drill 0.61 pad 1.02)
  Top 0.305: 43.33,54.94 43.46,54.92 44.53,55.99 47.08,55.99 47.09,56
  Top 0.406: v34.32,54.94 43.33,54.94
  Bottom 0.406: v34.32,54.94 33.36,53.66 33.36,40.33 35.59,38.42 35.59,25.15 40.03,20.71 40.03,20.64
P23  (via drill 0.61 pad 1.02)
  Top 0.305: 43.52,52.4 44.09,52.71 44.09,54.41 45.03,55.35 47.09,55.35
  Top 0.406: v34.95,52.4 43.52,52.4 43.59,52.4
  Bottom 0.406: v34.95,52.4 34.32,51.76 34.32,40.97 36.54,39.06 36.54,26.61 40.03,23.12 40.03,23.18
P24  (via drill 0.61 pad 1.02)
  Top 0.305: 43.65,49.85 43.97,50.17 44.29,51.82 44.73,52.46 44.73,53.98 45.45,54.7 47.09,54.7
  Top 0.406: v35.59,49.85 43.65,49.85 43.59,49.85
  Bottom 0.406: 40.03,25.73 39.97,25.73 | v35.59,49.85 35.27,49.54 35.27,41.6 37.49,39.7 37.49,28.2 39.97,25.73 | 39.97,25.73 40.03,25.66
P25
  Top 0.406: 21.23,28.27 22.5,27 27.27,27 28.55,28.28 28.6,28.27 40.03,28.27 47.02,28.27 50.83,24.46 52.73,24.46 55.08,22.79
P26
  Top 0.406: 55.14,27.81 54.95,27.63 54.64,27.63 52.73,27 50.83,27 47.02,30.8 40.03,30.8 37.49,30.8 36.22,29.53 22.5,29.53 21.23,30.8
P27  (via drill 0.61 pad 1.02)
  Top 0.305: 51.18,39.16 51.16,38.42 51.16,38.44 51.18,38.46 51.18,40.52 50.61,41.09 49.39,41.09
  Top 0.406: v47.74,39.07 49.39,41.09
  Bottom 0.406: 47.75,39.09 v47.74,39.07
  Bottom 0.61: 47.75,39.09 47.75,39.06 47.78,39.06 42.06,33.34 40.03,33.34
P30
  Bottom 0.61: 21.23,40.97 24.79,40.97
P31
  Bottom 0.61: 21.23,38.42 24.79,38.42
P32
  Bottom 0.61: 21.23,35.88 24.79,35.88
P33
  Bottom 0.61: 21.23,33.34 24.79,33.34
P34
  Top 0.406: 18.69,30.8 11.91,30.8
  Top 0.813: S1. 1.23,25.45 | 1.23,25.45 7.72,25.45 | 1.23,25.45 1.17,25.41
  Bottom 0.406: 24.79,30.8 24.73,30.8 23.46,29.53 19.96,29.53 18.69,30.8 17.49,30.8 16.54,29.85 16.54,27.82 15.39,26.68 9.55,26.68
  Bottom 0.813: 9.55,26.68 9.55,26.61 8.41,25.45 7.72,25.45
P35
  Top 0.406: 15.67,23.78 15.67,25.81 18.06,28.2 18.27,28.2 | 11.96,28.21 11.96,23.88 11.84,23.76 9.17,23.76
  Top 0.813: 15.67,23.78 15.66,23.83 15.66,23.76 9.17,23.76 9.16,23.76 S2. | 18.27,28.2 18.69,28.2 18.69,28.27 | 11.96,28.21 11.91,28.27
  Bottom 0.406: 18.69,28.27 19.96,27 23.58,27 24.79,28.2 24.79,28.27
RD\  (via drill 0.61 pad 1.02)
  Top 0.305: 41.28,44.77 43.5,44.77 43.97,44.31 43.97,44.27 44.82,42.35 47.09,42.35
  Top 0.406: v27.97,44.77 41.28,44.77
  Bottom 0.406: v27.97,44.77 27.97,40.65 27.33,40.01 27.33,26.93 26.44,26.04 26.44,24.77 24.79,23.12 24.79,23.18
RST  (via drill 0.61 pad 1.02)
  Top 0.406: 42.57,26.88 42.57,27 29.88,27 27.91,25.03 v27.97,25.09 | 18.69,43.51 18.69,43.57 17.04,43.57 16.41,42.93 16.41,34.93 15.77,34.3 13.5,34.3 11.91,35.88
  Bottom 0.406: v27.97,25.09 28.28,26.04 28.28,39.06 29.24,40.01 29.24,46.68 26.7,46.68 26.7,45.41 24.79,43.51
  Bottom 0.61: 24.79,43.51 21.23,43.51 18.69,43.51
RTS  (via drill 0.61 pad 1.02)
  Top 0.406: 84.48,13.03 81.31,13.03 80.04,14.29 70.51,14.29 69.24,15.56 47.71,15.56 46.44,14.29 38.19,14.29 33.24,19.31 30.82,19.31 29.24,20.96 v29.24,21.28 | 18.69,33.34 19.96,32.08 v29.55,32.08
  Bottom 0.406: v29.24,21.28 28.6,22.23 28.6,23.82 29.55,24.77 v29.55,32.08
RXD  (via drill 0.61 pad 1.02)
  Top 0.406: 84.48,10.48 81.31,10.48 80.04,11.76 70.51,11.76 67.97,14.29 48.92,14.29 47.65,13.03 36.54,13.03 31.51,18.05 31.51,18.08 v31.46,18.11 | 18.69,40.97 19.96,39.7 28.92,39.7 v30.19,38.42
  Bottom 0.406: v30.19,38.42 30.19,36.52 31.78,34.62 31.78,22.23 30.82,21.28 30.82,19.37 v31.46,18.11
TXD  (via drill 0.61 pad 1.02)
  Top 0.406: 84.48,15.56 81.31,15.56 80.04,16.84 38.25,16.84 34.51,20.58 32.79,20.58 32.77,20.61 32.77,20.64 v32.73,20.64 | 18.69,38.42 19.96,37.16 30.82,37.16 v32.09,36.52
  Bottom 0.406: v32.73,20.64 32.73,35.88 v32.09,36.52
WR\  (via drill 0.61 pad 1.02)
  Top 0.305: 41.3,42.23 43.14,42.23 43.21,42.17 43.65,41.7 47.09,41.7
  Top 0.406: v26.7,42.23 41.3,42.23
  Bottom 0.406: v26.7,42.23 26.38,40.97 26.38,27.38 24.79,25.79 24.79,25.73
(copper drawn outside any net)
  shapes: Top area x1

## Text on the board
Bottom: WWW | 8052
